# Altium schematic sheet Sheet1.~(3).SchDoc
size B; SheetNumber: 1; SheetTotal: 1
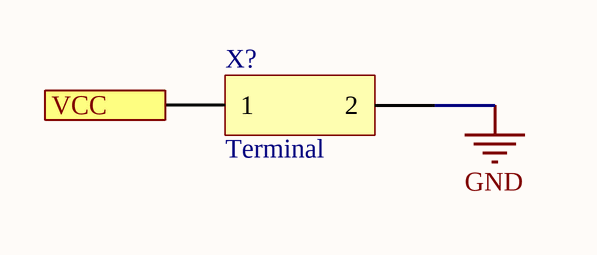
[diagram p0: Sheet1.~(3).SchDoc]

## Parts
X?  Terminal  [CON_TERMINAL_2POL]

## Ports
VCC

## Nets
GND: X?.2
VCC: X?.1 ; port VCC

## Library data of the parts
X? = CON_TERMINAL_2POL: Terminal Screw; Manufacturer_Name: Yageo; Manufacturer_Part_Number: RC0805FR-0710KL; Value: 10k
